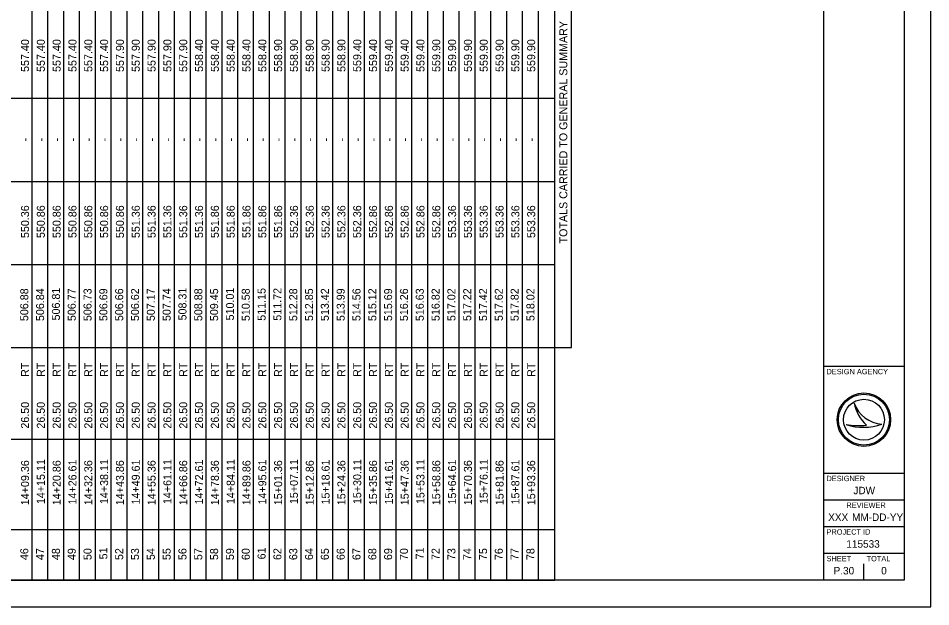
# Model space of a CAD drawing. Extents: x 0 to 34, y 0 to 22.
# Drawn here: x 16.93 to 34, y 0 to 11.01 of the extents above; entities that cross this region are included whole.
import ezdxf

# ---------------------------------------------------------------- set-up
doc = ezdxf.new("R2010")
doc.units = 0
for name, color, linetype in [('SH_Border', 7, 'Continuous'), ('SH_Cut_Line', 7, 'Continuous'), ('SH_Data', 7, 'Continuous'), ('SH_Text', 7, 'Continuous')]:
    doc.layers.add(name, color=color, linetype=linetype)

msp = doc.modelspace()

# ---------------------------------------------------------------- linework, layer by layer
at = {"layer": 'SH_Border'}
for p, q in [((32, 0.5), (32, 21.5)), ((32, 4.5), (33.5, 4.5)), ((32, 2.5), (33.5, 2.5)), ((32, 2), (33.5, 2)), ((32, 1.5), (33.5, 1.5)), ((32, 1), (33.5, 1))]:
    msp.add_line(p, q, dxfattribs=at)
msp.add_lwpolyline([(1.5, 21.5), (33.5, 21.5), (33.5, 0.5), (1.5, 0.5)], close=True, dxfattribs=at)
at = {"layer": 'SH_Cut_Line'}
msp.add_lwpolyline([(0, 0), (34, 0), (34, 22), (0, 22)], close=True, dxfattribs=at)
at = {"layer": 'SH_Data'}
for p, q in [((32.567, 3.81), (32.567, 3.81)), ((32.75, 3.5), (32.75, 3.5)), ((33.087, 3.419), (33.087, 3.419)), ((32.417, 3.41), (32.417, 3.41)), ((32.75, 0.5), (32.75, 0.8)), ((32.375, 0.675), (32.375, 0.675))]:
    msp.add_line(p, q, dxfattribs=at)
for radius in [0.5, 0.477, 0.477, 0.382]:
    msp.add_circle((32.75, 3.5), radius, dxfattribs=at)
for centre, radius, start, end in [((33.116, 3.998), 0.58, 198.9257, 198.9319), ((33.347, 3.97), 0.796, 191.6379, 191.6421), ((33.116, 3.998), 0.58, 198.9319, 267.1657), ((33.347, 3.97), 0.796, 191.6421, 226.0947), ((32.739, 4.37), 1.013, 251.4576, 290.0832), ((32.648, 4.654), 1.266, 259.4964, 259.4995), ((32.739, 4.37), 1.013, 251.4527, 251.4576), ((32.648, 4.654), 1.266, 259.4995, 276.6672)]:
    msp.add_arc(centre, radius, start, end, dxfattribs=at)
at = {"layer": 'SH_Text'}
for p, q in [((17.187, 0.5), (17.187, 21.5)), ((17.483, 0.5), (17.483, 21.5)), ((17.779, 0.5), (17.779, 21.5)), ((18.075, 0.5), (18.075, 21.5)), ((18.371, 0.5), (18.371, 21.5)), ((18.667, 0.5), (18.667, 21.5)), ((18.963, 0.5), (18.963, 21.5)), ((19.259, 0.5), (19.259, 21.5)), ((19.555, 0.5), (19.555, 21.5)), ((19.851, 0.5), (19.851, 21.5)), ((20.147, 0.5), (20.147, 21.5)), ((20.443, 0.5), (20.443, 21.5)), ((20.739, 0.5), (20.739, 21.5)), ((21.035, 0.5), (21.035, 21.5)), ((21.331, 0.5), (21.331, 21.5)), ((21.627, 0.5), (21.627, 21.5)), ((21.923, 0.5), (21.923, 21.5)), ((22.219, 0.5), (22.219, 21.5)), ((22.515, 0.5), (22.515, 21.5)), ((22.811, 0.5), (22.811, 21.5)), ((23.107, 0.5), (23.107, 21.5)), ((23.403, 0.5), (23.403, 21.5)), ((23.699, 0.5), (23.699, 21.5)), ((23.995, 0.5), (23.995, 21.5)), ((24.291, 0.5), (24.291, 21.5)), ((24.587, 0.5), (24.587, 21.5)), ((24.883, 0.5), (24.883, 21.5)), ((25.179, 0.5), (25.179, 21.5)), ((25.475, 0.5), (25.475, 21.5)), ((25.771, 0.5), (25.771, 21.5)), ((26.067, 0.5), (26.067, 21.5)), ((26.363, 0.5), (26.363, 21.5)), ((26.659, 0.5), (26.659, 21.5)), ((26.969, 0.5), (26.969, 21.5)), ((27.28, 4.851), (27.28, 21.5)), ((1.796, 9.513), (26.969, 9.513)), ((1.796, 7.959), (26.969, 7.959)), ((1.796, 6.405), (26.969, 6.405)), ((1.796, 4.851), (26.969, 4.851)), ((26.969, 4.851), (27.28, 4.851)), ((1.796, 3.134), (26.969, 3.134)), ((1.796, 1.447), (26.969, 1.447)), ((1.5, 0.5), (26.969, 0.5))]:
    msp.add_line(p, q, dxfattribs=at)

# ---------------------------------------------------------------- texts
at = {"layer": 'SH_Data'}
for s, height, p in [('DESIGN AGENCY', 0.1, (32.05, 4.35)), ('DESIGNER', 0.1, (32.05, 2.35)), ('JDW', 0.14, (32.553, 2.105)), ('REVIEWER', 0.1, (32.422, 1.85)), ('XXX', 0.14, (32.081, 1.605)), ('MM-DD-YY', 0.14, (32.527, 1.605)), ('PROJECT ID', 0.1, (32.05, 1.35)), ('115533', 0.14, (32.421, 1.105)), ('SHEET', 0.1, (32.05, 0.85)), ('TOTAL', 0.1, (32.8, 0.85)), ('P.30', 0.14, (32.182, 0.605)), ('0', 0.14, (33.073, 0.605))]:
    msp.add_text(s, height=height, dxfattribs=at).set_placement(p)
at = {"layer": 'SH_Text'}
for s, height, p in [('TOTALS CARRIED TO GENERAL SUMMARY', 0.14977, (27.2, 6.797)), ('557.40', 0.1498, (17.128, 10.006)), ('557.40', 0.1498, (17.424, 10.006)), ('557.40', 0.1498, (17.72, 10.006)), ('557.40', 0.1498, (18.016, 10.006)), ('557.40', 0.1498, (18.312, 10.006)), ('557.40', 0.1498, (18.608, 10.006)), ('557.90', 0.1498, (18.904, 10.006)), ('557.90', 0.1498, (19.2, 10.006)), ('557.90', 0.1498, (19.496, 10.006)), ('557.90', 0.1498, (19.792, 10.006)), ('557.90', 0.1498, (20.088, 10.006)), ('558.40', 0.1498, (20.384, 10.006)), ('558.40', 0.1498, (20.68, 10.006)), ('558.40', 0.1498, (20.976, 10.006)), ('558.40', 0.1498, (21.272, 10.006)), ('558.40', 0.1498, (21.568, 10.006)), ('558.90', 0.1498, (21.864, 10.006)), ('558.90', 0.1498, (22.16, 10.006)), ('558.90', 0.1498, (22.456, 10.006)), ('558.90', 0.1498, (22.752, 10.006)), ('558.90', 0.1498, (23.048, 10.006)), ('559.40', 0.1498, (23.344, 10.006)), ('559.40', 0.1498, (23.64, 10.006)), ('559.40', 0.1498, (23.936, 10.006)), ('559.40', 0.1498, (24.232, 10.006)), ('559.40', 0.1498, (24.527, 10.006)), ('559.90', 0.1498, (24.823, 10.006)), ('559.90', 0.1498, (25.119, 10.006)), ('559.90', 0.1498, (25.415, 10.006)), ('559.90', 0.1498, (25.711, 10.006)), ('559.90', 0.1498, (26.007, 10.006)), ('559.90', 0.1498, (26.303, 10.006)), ('559.90', 0.1498, (26.599, 10.006)), ('-', 0.15, (17.128, 8.707)), ('-', 0.15, (17.424, 8.707)), ('-', 0.15, (17.72, 8.707)), ('-', 0.15, (18.016, 8.707)), ('-', 0.15, (18.312, 8.707)), ('-', 0.15, (18.608, 8.707)), ('-', 0.15, (18.904, 8.707)), ('-', 0.15, (19.2, 8.707)), ('-', 0.15, (19.496, 8.707)), ('-', 0.15, (19.792, 8.707)), ('-', 0.15, (20.088, 8.707)), ('-', 0.15, (20.384, 8.707)), ('-', 0.15, (20.68, 8.707)), ('-', 0.15, (20.976, 8.707)), ('-', 0.15, (21.272, 8.707)), ('-', 0.15, (21.568, 8.707)), ('-', 0.15, (21.864, 8.707)), ('-', 0.15, (22.16, 8.707)), ('-', 0.15, (22.456, 8.707)), ('-', 0.15, (22.752, 8.707)), ('-', 0.15, (23.048, 8.707)), ('-', 0.15, (23.344, 8.707)), ('-', 0.15, (23.64, 8.707)), ('-', 0.15, (23.936, 8.707)), ('-', 0.15, (24.232, 8.707)), ('-', 0.15, (24.527, 8.707)), ('-', 0.15, (24.823, 8.707)), ('-', 0.15, (25.119, 8.707)), ('-', 0.15, (25.415, 8.707)), ('-', 0.15, (25.711, 8.707)), ('-', 0.15, (26.007, 8.707)), ('-', 0.15, (26.303, 8.707)), ('-', 0.15, (26.599, 8.707)), ('550.36', 0.1498, (17.128, 6.898)), ('550.86', 0.1498, (17.424, 6.898)), ('550.86', 0.1498, (17.72, 6.898)), ('550.86', 0.1498, (18.016, 6.898)), ('550.86', 0.1498, (18.312, 6.898)), ('550.86', 0.1498, (18.608, 6.898)), ('550.86', 0.1498, (18.904, 6.898)), ('551.36', 0.1498, (19.2, 6.898)), ('551.36', 0.1498, (19.496, 6.898)), ('551.36', 0.1498, (19.792, 6.898)), ('551.36', 0.1498, (20.088, 6.898)), ('551.36', 0.1498, (20.384, 6.898)), ('551.86', 0.1498, (20.68, 6.898)), ('551.86', 0.1498, (20.976, 6.898)), ('551.86', 0.1498, (21.272, 6.898)), ('551.86', 0.1498, (21.568, 6.898)), ('551.86', 0.1498, (21.864, 6.898)), ('552.36', 0.1498, (22.16, 6.898)), ('552.36', 0.1498, (22.456, 6.898)), ('552.36', 0.1498, (22.752, 6.898)), ('552.36', 0.1498, (23.048, 6.898)), ('552.36', 0.1498, (23.344, 6.898)), ('552.86', 0.1498, (23.64, 6.898)), ('552.86', 0.1498, (23.936, 6.898)), ('552.86', 0.1498, (24.232, 6.898)), ('552.86', 0.1498, (24.527, 6.898)), ('552.86', 0.1498, (24.823, 6.898)), ('553.36', 0.1498, (25.119, 6.898)), ('553.36', 0.1498, (25.415, 6.898)), ('553.36', 0.1498, (25.711, 6.898)), ('553.36', 0.1498, (26.007, 6.898)), ('553.36', 0.1498, (26.303, 6.898)), ('553.36', 0.1498, (26.599, 6.898)), ('506.88', 0.1498, (17.114, 5.344)), ('506.84', 0.1498, (17.41, 5.345)), ('506.81', 0.1498, (17.706, 5.357)), ('506.77', 0.1498, (18.002, 5.344)), ('506.73', 0.1498, (18.298, 5.344)), ('506.69', 0.1498, (18.594, 5.344)), ('506.66', 0.1498, (18.89, 5.344)), ('506.62', 0.1498, (19.186, 5.345)), ('507.17', 0.1498, (19.482, 5.344)), ('507.74', 0.1498, (19.778, 5.345)), ('508.31', 0.1498, (20.074, 5.357)), ('508.88', 0.1498, (20.37, 5.344)), ('509.45', 0.1498, (20.666, 5.344)), ('510.01', 0.1498, (20.962, 5.357)), ('510.58', 0.1498, (21.258, 5.344)), ('511.15', 0.1498, (21.554, 5.351)), ('511.72', 0.1498, (21.85, 5.352)), ('512.28', 0.1498, (22.146, 5.344)), ('512.85', 0.1498, (22.442, 5.344)), ('513.42', 0.1498, (22.738, 5.345)), ('513.99', 0.1498, (23.034, 5.344)), ('514.56', 0.1498, (23.33, 5.344)), ('515.12', 0.1498, (23.626, 5.345)), ('515.69', 0.1498, (23.922, 5.344)), ('516.26', 0.1498, (24.218, 5.344)), ('516.63', 0.1498, (24.514, 5.344)), ('516.82', 0.1498, (24.81, 5.345)), ('517.02', 0.1498, (25.106, 5.345)), ('517.22', 0.1498, (25.402, 5.345)), ('517.42', 0.1498, (25.698, 5.345)), ('517.62', 0.1498, (25.993, 5.345)), ('517.82', 0.1498, (26.289, 5.345)), ('518.02', 0.1498, (26.585, 5.345)), ('RT', 0.1498, (17.128, 4.3)), ('RT', 0.1498, (17.424, 4.3)), ('RT', 0.1498, (17.72, 4.3)), ('RT', 0.1498, (18.016, 4.3)), ('RT', 0.1498, (18.312, 4.3)), ('RT', 0.1498, (18.608, 4.3)), ('RT', 0.1498, (18.904, 4.3)), ('RT', 0.1498, (19.2, 4.3)), ('RT', 0.1498, (19.496, 4.3)), ('RT', 0.1498, (19.792, 4.3)), ('RT', 0.1498, (20.088, 4.3)), ('RT', 0.1498, (20.384, 4.3)), ('RT', 0.1498, (20.68, 4.3)), ('RT', 0.1498, (20.976, 4.3)), ('RT', 0.1498, (21.272, 4.3)), ('RT', 0.1498, (21.568, 4.3)), ('RT', 0.1498, (21.864, 4.3)), ('RT', 0.1498, (22.16, 4.3)), ('RT', 0.1498, (22.456, 4.3)), ('RT', 0.1498, (22.752, 4.3)), ('RT', 0.1498, (23.048, 4.3)), ('RT', 0.1498, (23.344, 4.3)), ('RT', 0.1498, (23.64, 4.3)), ('RT', 0.1498, (23.936, 4.3)), ('RT', 0.1498, (24.232, 4.3)), ('RT', 0.1498, (24.527, 4.3)), ('RT', 0.1498, (24.823, 4.3)), ('RT', 0.1498, (25.119, 4.3)), ('RT', 0.1498, (25.415, 4.3)), ('RT', 0.1498, (25.711, 4.3)), ('RT', 0.1498, (26.007, 4.3)), ('RT', 0.1498, (26.303, 4.3)), ('RT', 0.1498, (26.599, 4.3)), ('26.50', 0.1498, (17.128, 3.332)), ('26.50', 0.1498, (17.424, 3.332)), ('26.50', 0.1498, (17.72, 3.332)), ('26.50', 0.1498, (18.016, 3.332)), ('26.50', 0.1498, (18.312, 3.332)), ('26.50', 0.1498, (18.608, 3.332)), ('26.50', 0.1498, (18.904, 3.332)), ('26.50', 0.1498, (19.2, 3.332)), ('26.50', 0.1498, (19.496, 3.332)), ('26.50', 0.1498, (19.792, 3.332)), ('26.50', 0.1498, (20.088, 3.332)), ('26.50', 0.1498, (20.384, 3.332)), ('26.50', 0.1498, (20.68, 3.332)), ('26.50', 0.1498, (20.976, 3.332)), ('26.50', 0.1498, (21.272, 3.332)), ('26.50', 0.1498, (21.568, 3.332)), ('26.50', 0.1498, (21.864, 3.332)), ('26.50', 0.1498, (22.16, 3.332)), ('26.50', 0.1498, (22.456, 3.332)), ('26.50', 0.1498, (22.752, 3.332)), ('26.50', 0.1498, (23.048, 3.332)), ('26.50', 0.1498, (23.344, 3.332)), ('26.50', 0.1498, (23.64, 3.332)), ('26.50', 0.1498, (23.936, 3.332)), ('26.50', 0.1498, (24.232, 3.332)), ('26.50', 0.1498, (24.527, 3.332)), ('26.50', 0.1498, (24.823, 3.332)), ('26.50', 0.1498, (25.119, 3.332)), ('26.50', 0.1498, (25.415, 3.332)), ('26.50', 0.1498, (25.711, 3.332)), ('26.50', 0.1498, (26.007, 3.332)), ('26.50', 0.1498, (26.303, 3.332)), ('26.50', 0.1498, (26.599, 3.332)), ('14+09.36', 0.1498, (17.128, 1.9)), ('14+15.11', 0.1498, (17.424, 1.92)), ('14+20.86', 0.1498, (17.72, 1.9)), ('14+26.61', 0.1498, (18.016, 1.913)), ('14+32.36', 0.1498, (18.312, 1.9)), ('14+38.11', 0.1498, (18.608, 1.92)), ('14+43.86', 0.1498, (18.904, 1.9)), ('14+49.61', 0.1498, (19.2, 1.913)), ('14+55.36', 0.1498, (19.496, 1.9)), ('14+61.11', 0.1498, (19.792, 1.92)), ('14+66.86', 0.1498, (20.088, 1.9)), ('14+72.61', 0.1498, (20.384, 1.913)), ('14+78.36', 0.1498, (20.68, 1.9)), ('14+84.11', 0.1498, (20.976, 1.92)), ('14+89.86', 0.1498, (21.272, 1.9)), ('14+95.61', 0.1498, (21.568, 1.913)), ('15+01.36', 0.1498, (21.864, 1.9)), ('15+07.11', 0.1498, (22.16, 1.92)), ('15+12.86', 0.1498, (22.456, 1.9)), ('15+18.61', 0.1498, (22.752, 1.913)), ('15+24.36', 0.1498, (23.048, 1.9)), ('15+30.11', 0.1498, (23.344, 1.92)), ('15+35.86', 0.1498, (23.64, 1.9)), ('15+41.61', 0.1498, (23.936, 1.913)), ('15+47.36', 0.1498, (24.232, 1.9)), ('15+53.11', 0.1498, (24.527, 1.92)), ('15+58.86', 0.1498, (24.823, 1.9)), ('15+64.61', 0.1498, (25.119, 1.913)), ('15+70.36', 0.1498, (25.415, 1.9)), ('15+76.11', 0.1498, (25.711, 1.92)), ('15+81.86', 0.1498, (26.007, 1.9)), ('15+87.61', 0.1498, (26.303, 1.913)), ('15+93.36', 0.1498, (26.599, 1.9)), ('46', 0.1498, (17.114, 0.873)), ('47', 0.1498, (17.41, 0.873)), ('48', 0.1498, (17.706, 0.873)), ('49', 0.1498, (18.002, 0.873)), ('50', 0.1498, (18.298, 0.873)), ('51', 0.1498, (18.594, 0.886)), ('52', 0.1498, (18.89, 0.874)), ('53', 0.1498, (19.186, 0.873)), ('54', 0.1498, (19.482, 0.873)), ('55', 0.1498, (19.778, 0.873)), ('56', 0.1498, (20.074, 0.873)), ('57', 0.1498, (20.37, 0.873)), ('58', 0.1498, (20.666, 0.873)), ('59', 0.1498, (20.962, 0.873)), ('60', 0.1498, (21.258, 0.873)), ('61', 0.1498, (21.554, 0.886)), ('62', 0.1498, (21.85, 0.874)), ('63', 0.1498, (22.146, 0.873)), ('64', 0.1498, (22.442, 0.873)), ('65', 0.1498, (22.738, 0.873)), ('66', 0.1498, (23.034, 0.873)), ('67', 0.1498, (23.33, 0.873)), ('68', 0.1498, (23.626, 0.873)), ('69', 0.1498, (23.922, 0.873)), ('70', 0.1498, (24.218, 0.873)), ('71', 0.1498, (24.514, 0.886)), ('72', 0.1498, (24.81, 0.874)), ('73', 0.1498, (25.106, 0.873)), ('74', 0.1498, (25.402, 0.873)), ('75', 0.1498, (25.698, 0.873)), ('76', 0.1498, (25.993, 0.873)), ('77', 0.1498, (26.289, 0.873)), ('78', 0.1498, (26.585, 0.873))]:
    msp.add_text(s, height=height, rotation=90, dxfattribs=at).set_placement(p)

doc.saveas('drawing.dxf')
